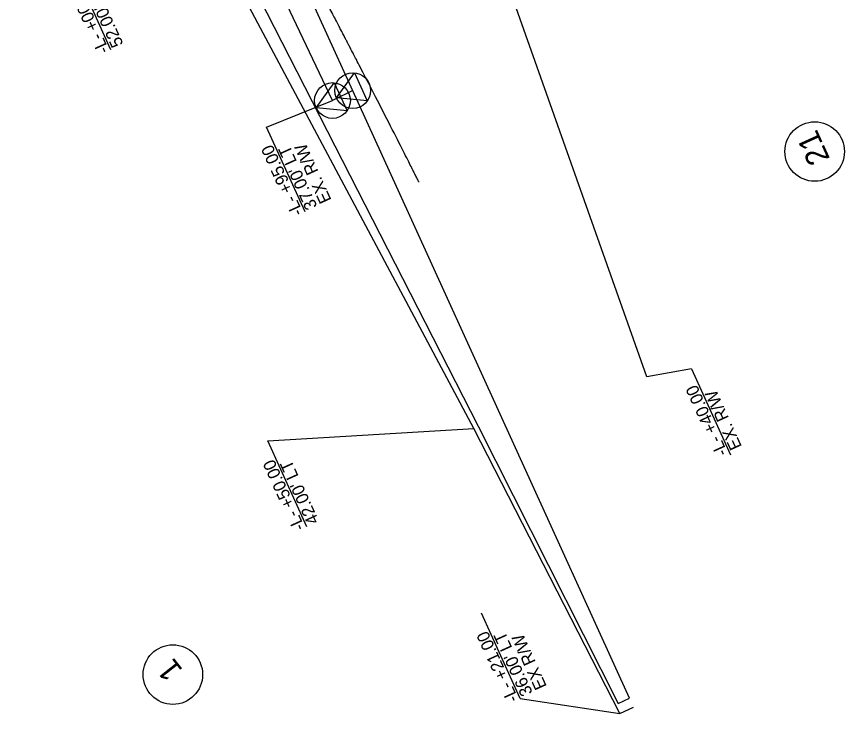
# Model space of a CAD drawing. Extents: x 2097272 to 2098144, y 685104 to 689282.
# Drawn here: x 2097804 to 2098137.7, y 685104.3 to 685385.3 of the extents above; entities that cross this region are included whole.
import ezdxf

# ---------------------------------------------------------------- set-up
doc = ezdxf.new("R2010")
doc.units = 0
for name, color, linetype in [('Prop Easement Construction', 7, 'Continuous'), ('Prop Easement Construction Station Offsets', 7, 'Continuous'), ('Prop Parcel Number CELL', 7, 'Continuous'), ('Prop ROW Marker CELL', 7, 'Continuous'), ('Prop ROW RW Lines', 7, 'Continuous'), ('Prop ROW Station Offsets', 7, 'Continuous'), ('Scratch_Level_1', 7, 'Continuous'), ('Scratch_Level_6', 7, 'Continuous')]:
    doc.layers.add(name, color=color, linetype=linetype)

msp = doc.modelspace()

# ---------------------------------------------------------------- linework, layer by layer
at = {"layer": 'Prop Easement Construction'}
for p, q in [((2098058, 685239.98), (2097983.31, 685451.34)), ((2097988.32, 685219.26), (2097871.22, 685439.01)), ((2098047.21, 685104.33), (2097988.32, 685219.26)), ((2098047.21, 685104.33), (2098052.67, 685106.82))]:
    msp.add_line(p, q, dxfattribs=at)
at = {"layer": 'Prop Easement Construction Station Offsets'}
for p, q in [((2097842.07, 685371.9), (2097826.5, 685406.12)), ((2098076.05, 685243.22), (2098058, 685239.98)), ((2098076.05, 685243.22), (2098091.79, 685208.64)), ((2097905.29, 685214.27), (2097988.32, 685219.26)), ((2097921.07, 685179.58), (2097905.29, 685214.27)), ((2098007.04, 685110.34), (2097991.36, 685144.79)), ((2098007.04, 685110.34), (2098047.21, 685104.33))]:
    msp.add_line(p, q, dxfattribs=at)
at = {"layer": 'Prop Parcel Number CELL'}
for centre in [(2098125.71, 685330.88), (2097867.04, 685120)]:
    msp.add_circle(centre, 12, dxfattribs=at)
at = {"layer": 'Prop ROW Marker CELL'}
for p, q in [((2097939.53, 685355.46), (2097939.53, 685355.46)), ((2097931.37, 685351.45), (2097931.37, 685351.45))]:
    msp.add_line(p, q, dxfattribs=at)
for points in [[(2097945.39, 685351.26), (2097932.98, 685352.47), (2097940.22, 685362.64)], [(2097937.23, 685347.25), (2097924.81, 685348.47), (2097932.06, 685358.63)]]:
    msp.add_lwpolyline(points, close=True, dxfattribs=at)
for centre in [(2097939.53, 685355.46), (2097931.37, 685351.45)]:
    msp.add_circle(centre, 7.2, dxfattribs=at)
at = {"layer": 'Prop ROW RW Lines'}
for p, q in [((2097931.37, 685351.45), (2097804.03, 685618.88)), ((2097939.53, 685355.46), (2097931.37, 685351.45))]:
    msp.add_line(p, q, dxfattribs=at)
at = {"layer": 'Prop ROW Station Offsets'}
for p, q in [((2097904.81, 685340.68), (2097931.37, 685351.45)), ((2097920.35, 685306.54), (2097904.81, 685340.68))]:
    msp.add_line(p, q, dxfattribs=at)
at = {"layer": 'Scratch_Level_1'}
for points in [[(2097937.09, 685375.47), (2097936.93, 685375.77), (2097936.78, 685376.07), (2097936.55, 685376.51), (2097936.47, 685376.66), (2097936.35, 685376.88), (2097936.32, 685376.96), (2097936.24, 685377.11), (2097935.89, 685377.78), (2097934.93, 685379.63), (2097932.76, 685383.78), (2097929.66, 685389.71), (2097927.02, 685394.74), (2097925.62, 685397.41), (2097925.31, 685398), (2097925.15, 685398.3), (2097924.68, 685399.18), (2097924.37, 685399.78), (2097923.9, 685400.67), (2097923.74, 685400.96), (2097923.43, 685401.56), (2097923.28, 685401.85), (2097923.08, 685402.22), (2097923.04, 685402.3), (2097922.96, 685402.45), (2097922.85, 685402.67), (2097922.57, 685403.19), (2097919.84, 685408.39), (2097915.95, 685415.82), (2097911.61, 685424.15), (2097909.44, 685428.32), (2097908.52, 685430.11), (2097907.9, 685431.3), (2097907.59, 685431.89), (2097907.28, 685432.49)], [(2097966.26, 685318.47), (2097966.11, 685318.77), (2097965.96, 685319.07), (2097965.73, 685319.51), (2097965.64, 685319.7), (2097965.54, 685319.89), (2097965.51, 685319.96), (2097965.49, 685320), (2097965.43, 685320.11), (2097965.09, 685320.78), (2097964.15, 685322.64), (2097962.05, 685326.81), (2097957.83, 685335.14), (2097951.77, 685347.02), (2097945.68, 685358.89), (2097941.39, 685367.18), (2097939.24, 685371.33), (2097938.32, 685373.11), (2097937.7, 685374.29), (2097937.4, 685374.88), (2097937.09, 685375.47)]]:
    msp.add_open_spline(points, degree=3, dxfattribs=at)
at = {"layer": 'Scratch_Level_6'}
for p, q in [((2097899.86, 685396.86), (2097990.14, 685220.09)), ((2097990.14, 685220.09), (2098046.46, 685108.39)), ((2098046.46, 685108.39), (2098051.01, 685110.46))]:
    msp.add_line(p, q, dxfattribs=at)
msp.add_lwpolyline([(2098051.01, 685110.46), (2097957.82, 685315.25), (2097910.14, 685420.03)], dxfattribs=at)

# ---------------------------------------------------------------- texts
at = {"layer": 'Prop Easement Construction Station Offsets'}
for s, p in [('-L- +00.00', (2097841.5, 685371.64)), ("52.00' LT", (2097847.19, 685374.23)), ('-L- +40.00', (2098090.78, 685209.34)), ('EX. R/W', (2098096.47, 685211.93)), ('-L- +50.00', (2097920.37, 685179.27)), ("42.00' LT", (2097926.06, 685181.85)), ('-L- +21.00', (2098006.47, 685110.08)), ("36.00' LT", (2098012.16, 685112.67)), ('EX R/W', (2098017.85, 685115.26))]:
    msp.add_text(s, height=5, rotation=114.4674, dxfattribs=at).set_placement(p)
at = {"layer": 'Prop Parcel Number CELL'}
for s, rotation, p in [('21', 114.4674, (2098131.98, 685327.97)), ('1', 128.3605, (2097871.32, 685121.84))]:
    msp.add_text(s, height=9, rotation=rotation, dxfattribs=at).set_placement(p)
at = {"layer": 'Prop ROW Station Offsets'}
for s, p in [('-L- +95.00', (2097919.67, 685306.16)), ("37.00' LT", (2097925.36, 685308.75)), ('EX. R/W', (2097931.05, 685311.33))]:
    msp.add_text(s, height=5, rotation=114.4674, dxfattribs=at).set_placement(p)

doc.saveas('drawing.dxf')
